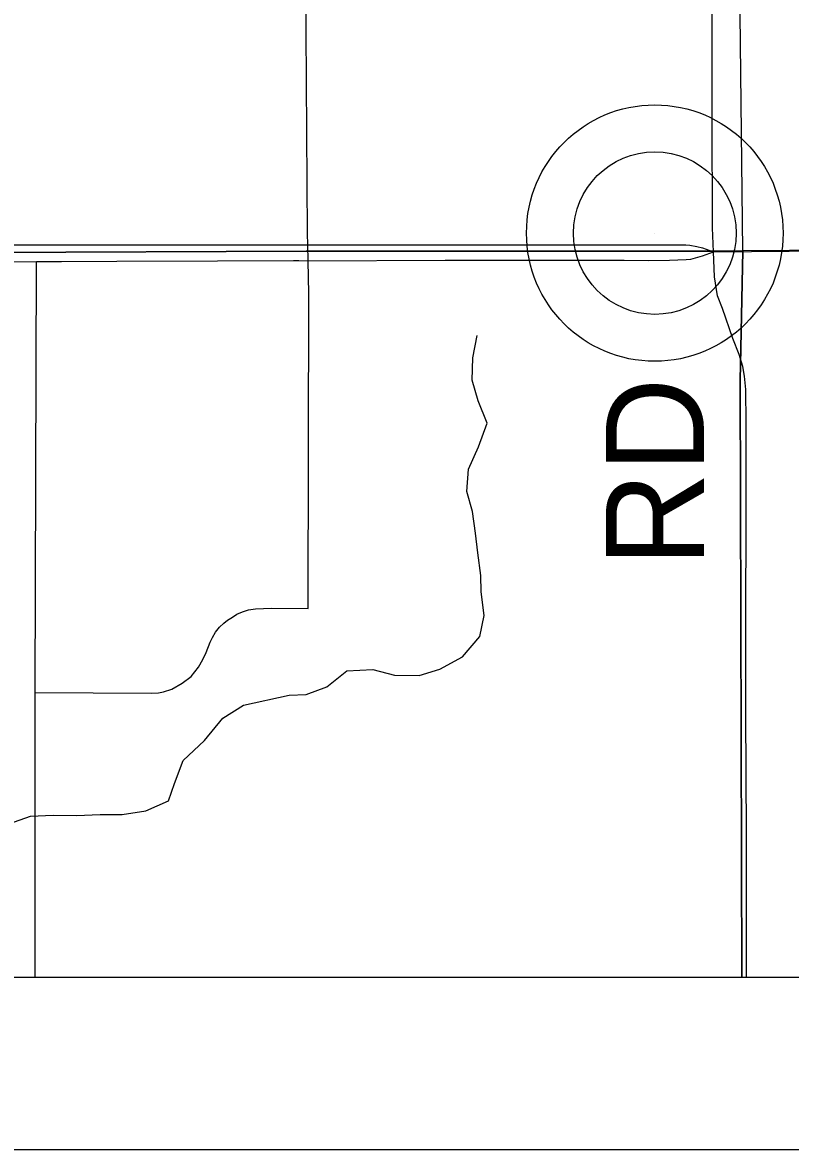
# Model space of a CAD drawing. Extents: x 0 to 34, y 0 to 22.
# Drawn here: x 2.448 to 2.893, y 14 to 14.654 of the extents above; entities that cross this region are included whole.
import ezdxf

# ---------------------------------------------------------------- set-up
doc = ezdxf.new("R2010")
doc.units = 0
for name, color, linetype in [('GM_X_Corporation', 7, 'Continuous'), ('GM_X_County_Road', 7, 'Continuous'), ('GM_X_County_Road_Text', 7, 'Continuous'), ('GM_X_Minor_River', 7, 'Continuous'), ('GM_X_State_Route', 7, 'Continuous'), ('GM_X_Township_Road', 7, 'Continuous'), ('GM_X_Unincorporated', 7, 'Continuous'), ('GM_X_Unincorporated_Location', 7, 'Continuous'), ('SH_Data', 7, 'Continuous')]:
    doc.layers.add(name, color=color, linetype=linetype)

msp = doc.modelspace()

# ---------------------------------------------------------------- linework, layer by layer
at = {"layer": 'GM_X_Corporation'}
for points in [[(2.1, 20.9), (2.1, 14.1), (7.97338, 14.1), (7.97262, 14.54527), (7.97647, 15.26367), (7.97915, 15.54806), (7.97899, 15.59876), (7.98085, 15.71925), (7.98068, 15.90776), (7.98205, 16.24869), (7.98249, 16.33947), (7.98185, 16.39822), (7.9825, 16.60771), (7.9838, 16.79684), (7.98767, 17.38714), (7.98908, 17.54975), (7.991, 17.77271), (7.99007, 18.1613)], [(3.735, 14.52753), (3.38389, 14.52643), (3.3511, 14.525), (2.86545, 14.52142), (2.85021, 15.87677), (2.84883, 16.19997), (2.84871, 16.22733), (2.84865, 16.23198), (2.84766, 16.31355), (2.84764, 16.31575), (2.84767, 16.78338), (2.83696, 17.92592), (2.82932, 18.71542)]]:
    msp.add_lwpolyline(points, dxfattribs=at)
for points in [[(2.1, 19.01666), (2.1, 14.51787), (2.22133, 14.5194), (2.29576, 14.51985), (2.35733, 14.52033), (2.37669, 14.52061), (2.42616, 14.52053), (2.6122, 14.52122), (2.84828, 14.52126), (2.86545, 14.52142), (2.85021, 15.87677), (2.84883, 16.19997), (2.84871, 16.22733), (2.84865, 16.23198), (2.84766, 16.31355), (2.84764, 16.31575), (2.84767, 16.78338), (2.83696, 17.92592), (2.82932, 18.71542), (2.82466, 19.03234), (2.43916, 19.024), (2.42876, 19.02377), (2.42097, 19.0236)], [(2.86492, 14.1), (7.97338, 14.1), (7.97262, 14.54527), (7.08712, 14.54286), (7.01972, 14.54267), (6.49407, 14.54124), (6.14758, 14.53974), (5.46444, 14.53736), (4.52117, 14.531), (4.37721, 14.52959), (4.3422, 14.53065), (3.735, 14.52753), (3.38389, 14.52643), (3.3511, 14.525), (2.86545, 14.52142), (2.8638, 14.44612)], [(2.1, 14.51787), (2.1, 14.1), (2.86492, 14.1), (2.8638, 14.44612), (2.86545, 14.52142), (2.84828, 14.52126), (2.6122, 14.52122), (2.42616, 14.52053), (2.37669, 14.52061), (2.35733, 14.52033), (2.29576, 14.51985), (2.22133, 14.5194)]]:
    msp.add_lwpolyline(points, close=True, dxfattribs=at)
at = {"layer": 'GM_X_County_Road'}
for points in [[(2.84844, 14.52084), (2.84776, 14.53471), (2.84766, 14.59982), (2.84761, 14.74053), (2.84776, 14.92075), (2.84762, 14.9485), (2.84748, 14.97757), (2.84718, 15.03351), (2.84704, 15.05875), (2.84691, 15.08413), (2.84663, 15.13462), (2.84652, 15.14396), (2.84672, 15.24598), (2.84694, 15.30251), (2.84712, 15.34684), (2.84726, 15.38098), (2.84745, 15.42916), (2.84658, 15.87612)], [(2.86745, 14.1), (2.86751, 14.18321), (2.86718, 14.25325), (2.86739, 14.42163), (2.86723, 14.44102), (2.86644, 14.44876), (2.86543, 14.45429), (2.86324, 14.46132), (2.85959, 14.47055), (2.85357, 14.48804), (2.8508, 14.49525), (2.84904, 14.50628), (2.84844, 14.52084)]]:
    msp.add_lwpolyline(points, dxfattribs=at)
at = {"layer": 'GM_X_Minor_River'}
msp.add_lwpolyline([(2.4398, 14.18896), (2.45221, 14.19335), (2.46543, 14.19396), (2.47905, 14.19382), (2.49266, 14.19444), (2.50552, 14.19429), (2.5191, 14.19642), (2.53224, 14.20234), (2.53585, 14.21228), (2.54091, 14.22565), (2.55318, 14.23724), (2.56392, 14.25034), (2.5759, 14.25776), (2.60228, 14.26353), (2.6121, 14.26408), (2.62413, 14.26847), (2.63569, 14.27778), (2.65081, 14.27842), (2.66335, 14.27523), (2.67772, 14.2751), (2.68976, 14.27872), (2.70288, 14.28578), (2.71288, 14.29773), (2.71531, 14.30991), (2.71356, 14.32354), (2.71339, 14.33302), (2.71165, 14.34627), (2.71031, 14.35764), (2.70858, 14.37013), (2.70535, 14.38184), (2.70626, 14.39475), (2.71208, 14.40776), (2.71713, 14.42151), (2.71199, 14.43432), (2.70838, 14.4464), (2.70891, 14.45931), (2.71132, 14.47225)], dxfattribs=at)
at = {"layer": 'GM_X_State_Route'}
for points in [[(2.1, 14.52283), (2.15107, 14.52349), (2.22254, 14.52452), (2.22369, 14.52452), (2.24308, 14.52483), (2.29622, 14.52484), (2.35999, 14.52486), (2.37851, 14.52487), (2.42643, 14.52489), (2.61312, 14.52494), (2.8324, 14.52501), (2.83467, 14.52482), (2.83867, 14.52397), (2.84195, 14.52313), (2.84844, 14.52084)], [(2.84844, 14.52084), (3.04606, 14.52267), (3.13277, 14.52364), (3.18691, 14.52425), (3.21898, 14.52457), (3.26025, 14.52499), (3.28852, 14.52528), (3.35122, 14.52623)], [(2.60483, 14.51576), (2.60784, 14.51577), (2.61333, 14.5156), (2.69281, 14.51596), (2.74411, 14.51608), (2.7965, 14.51598), (2.81041, 14.51576), (2.82289, 14.51607), (2.83257, 14.5164), (2.83528, 14.5167), (2.84202, 14.51864), (2.84844, 14.52084)], [(2.42643, 14.51512), (2.45583, 14.51519), (2.47026, 14.51527), (2.5023, 14.51553), (2.56074, 14.51566), (2.60483, 14.51576)]]:
    msp.add_lwpolyline(points, dxfattribs=at)
at = {"layer": 'GM_X_Township_Road'}
for points in [[(2.61333, 14.5156), (2.61312, 14.52494), (2.61297, 14.53143), (2.6119, 14.67863)], [(2.45492, 14.1), (2.45508, 14.24751), (2.45508, 14.26507), (2.45583, 14.51519)], [(2.61332, 14.31384), (2.61363, 14.4967), (2.61333, 14.5156)], [(2.45508, 14.26507), (2.5223, 14.26478), (2.52647, 14.26501), (2.52942, 14.26547), (2.53421, 14.26706), (2.54033, 14.27052), (2.54551, 14.27444), (2.54974, 14.27977), (2.55226, 14.28433), (2.55414, 14.2884), (2.5565, 14.29437), (2.55775, 14.29704), (2.55964, 14.30018), (2.56184, 14.30301), (2.56435, 14.30536), (2.56654, 14.30709), (2.56937, 14.30897), (2.57188, 14.31054), (2.57518, 14.31195), (2.57863, 14.31305), (2.58271, 14.31368), (2.59197, 14.31415), (2.61332, 14.31384)]]:
    msp.add_lwpolyline(points, dxfattribs=at)
at = {"layer": 'GM_X_Unincorporated'}
for radius in [0.0744, 0.04716]:
    msp.add_circle((2.81435, 14.53174), radius, dxfattribs=at)
at = {"layer": 'GM_X_Unincorporated_Location'}
msp.add_line((2.81435, 14.53174), (2.81435, 14.53174), dxfattribs=at)
at = {"layer": 'SH_Data'}
for p, q in [((2.1, 14.1), (8.9, 14.1)), ((2, 14), (9, 14))]:
    msp.add_line(p, q, dxfattribs=at)

# ---------------------------------------------------------------- texts
at = {"layer": 'GM_X_County_Road_Text'}
msp.add_text('RD', height=0.056818, rotation=90, dxfattribs=at).set_placement((2.84282, 14.33807))

doc.saveas('drawing.dxf')
